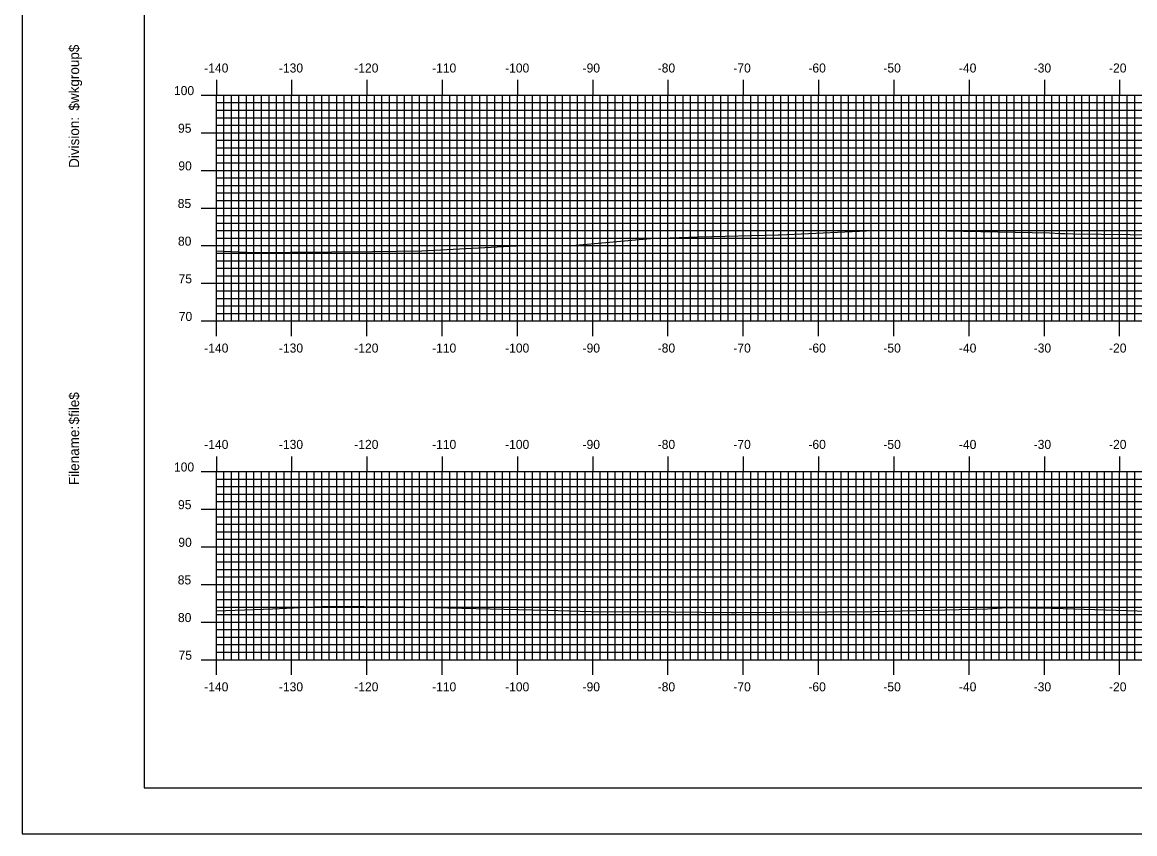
# Model space of a CAD drawing. Extents: x 856716 to 857060, y 364765 to 364985.
# Drawn here: x 856716.5 to 856864.3, y 364765.2 to 364873 of the extents above; entities that cross this region are included whole.
import ezdxf

# ---------------------------------------------------------------- set-up
doc = ezdxf.new("R2010")
doc.units = 0
for name, color, linetype in [('BORDER', 7, 'Continuous'), ('H_V ANNOTATION', 7, 'Continuous'), ('MAJOR', 7, 'Continuous'), ('MINOR', 7, 'Continuous'), ('PLOT BOUNDARY', 7, 'Continuous'), ('S_Roadway_Centerline', 7, 'Continuous')]:
    doc.layers.add(name, color=color, linetype=linetype)

msp = doc.modelspace()

# ---------------------------------------------------------------- linework, layer by layer
at = {"layer": 'BORDER'}
msp.add_lwpolyline([(856732.68, 364771.3), (857052.68, 364771.3), (857052.68, 364981.3), (856732.68, 364981.3)], close=True, dxfattribs=at)
at = {"layer": 'MAJOR'}
for p, q in [((856742.28, 364865.31), (856742.28, 364863.3)), ((856752.28, 364865.31), (856752.28, 364863.3)), ((856762.28, 364865.31), (856762.28, 364863.3)), ((856772.28, 364865.31), (856772.28, 364863.3)), ((856782.28, 364865.31), (856782.28, 364863.3)), ((856792.28, 364865.31), (856792.28, 364863.3)), ((856802.28, 364865.31), (856802.28, 364863.3)), ((856812.28, 364865.31), (856812.28, 364863.3)), ((856822.28, 364865.31), (856822.28, 364863.3)), ((856832.28, 364865.31), (856832.28, 364863.3)), ((856842.28, 364865.31), (856842.28, 364863.3)), ((856852.28, 364865.31), (856852.28, 364863.3)), ((856862.28, 364865.31), (856862.28, 364863.3)), ((856740.28, 364863.3), (856742.28, 364863.3)), ((856742.28, 364863.3), (857022.28, 364863.3)), ((856742.28, 364833.3), (856742.28, 364863.3)), ((856742.28, 364833.3), (856742.28, 364863.3)), ((856742.28, 364863.3), (857022.28, 364863.3)), ((856752.28, 364833.3), (856752.28, 364863.3)), ((856762.28, 364833.3), (856762.28, 364863.3)), ((856772.28, 364833.3), (856772.28, 364863.3)), ((856782.28, 364833.3), (856782.28, 364863.3)), ((856792.28, 364833.3), (856792.28, 364863.3)), ((856802.28, 364833.3), (856802.28, 364863.3)), ((856812.28, 364833.3), (856812.28, 364863.3)), ((856822.28, 364833.3), (856822.28, 364863.3)), ((856832.28, 364833.3), (856832.28, 364863.3)), ((856842.28, 364833.3), (856842.28, 364863.3)), ((856852.28, 364833.3), (856852.28, 364863.3)), ((856862.28, 364833.3), (856862.28, 364863.3)), ((856740.28, 364858.3), (856742.28, 364858.3)), ((856742.28, 364858.3), (857022.28, 364858.3)), ((856740.28, 364853.3), (856742.28, 364853.3)), ((856742.28, 364853.3), (857022.28, 364853.3)), ((856740.28, 364848.3), (856742.28, 364848.3)), ((856742.28, 364848.3), (857022.28, 364848.3)), ((856740.28, 364843.3), (856742.28, 364843.3)), ((856742.28, 364843.3), (857022.28, 364843.3)), ((856740.28, 364838.3), (856742.28, 364838.3)), ((856742.28, 364838.3), (857022.28, 364838.3)), ((856740.28, 364833.3), (856742.28, 364833.3)), ((856742.28, 364833.3), (857022.28, 364833.3)), ((856742.28, 364833.3), (857022.28, 364833.3)), ((856742.28, 364831.3), (856742.28, 364833.3)), ((856752.28, 364831.3), (856752.28, 364833.3)), ((856762.28, 364831.3), (856762.28, 364833.3)), ((856772.28, 364831.3), (856772.28, 364833.3)), ((856782.28, 364831.3), (856782.28, 364833.3)), ((856792.28, 364831.3), (856792.28, 364833.3)), ((856802.28, 364831.3), (856802.28, 364833.3)), ((856812.28, 364831.3), (856812.28, 364833.3)), ((856822.28, 364831.3), (856822.28, 364833.3)), ((856832.28, 364831.3), (856832.28, 364833.3)), ((856842.28, 364831.3), (856842.28, 364833.3)), ((856852.28, 364831.3), (856852.28, 364833.3)), ((856862.28, 364831.3), (856862.28, 364833.3)), ((856742.28, 364815.31), (856742.28, 364813.3)), ((856752.28, 364815.31), (856752.28, 364813.3)), ((856762.28, 364815.31), (856762.28, 364813.3)), ((856772.28, 364815.31), (856772.28, 364813.3)), ((856782.28, 364815.31), (856782.28, 364813.3)), ((856792.28, 364815.31), (856792.28, 364813.3)), ((856802.28, 364815.31), (856802.28, 364813.3)), ((856812.28, 364815.31), (856812.28, 364813.3)), ((856822.28, 364815.31), (856822.28, 364813.3)), ((856832.28, 364815.31), (856832.28, 364813.3)), ((856842.28, 364815.31), (856842.28, 364813.3)), ((856852.28, 364815.31), (856852.28, 364813.3)), ((856862.28, 364815.31), (856862.28, 364813.3)), ((856740.28, 364813.3), (856742.28, 364813.3)), ((856742.28, 364813.3), (857022.28, 364813.3)), ((856742.28, 364788.3), (856742.28, 364813.3)), ((856742.28, 364788.3), (856742.28, 364813.3)), ((856742.28, 364813.3), (857022.28, 364813.3)), ((856752.28, 364788.3), (856752.28, 364813.3)), ((856762.28, 364788.3), (856762.28, 364813.3)), ((856772.28, 364788.3), (856772.28, 364813.3)), ((856782.28, 364788.3), (856782.28, 364813.3)), ((856792.28, 364788.3), (856792.28, 364813.3)), ((856802.28, 364788.3), (856802.28, 364813.3)), ((856812.28, 364788.3), (856812.28, 364813.3)), ((856822.28, 364788.3), (856822.28, 364813.3)), ((856832.28, 364788.3), (856832.28, 364813.3)), ((856842.28, 364788.3), (856842.28, 364813.3)), ((856852.28, 364788.3), (856852.28, 364813.3)), ((856862.28, 364788.3), (856862.28, 364813.3)), ((856740.28, 364808.3), (856742.28, 364808.3)), ((856742.28, 364808.3), (857022.28, 364808.3)), ((856740.28, 364803.3), (856742.28, 364803.3)), ((856742.28, 364803.3), (857022.28, 364803.3)), ((856740.28, 364798.3), (856742.28, 364798.3)), ((856742.28, 364798.3), (857022.28, 364798.3)), ((856740.28, 364793.3), (856742.28, 364793.3)), ((856742.28, 364793.3), (857022.28, 364793.3)), ((856740.28, 364788.3), (856742.28, 364788.3)), ((856742.28, 364788.3), (857022.28, 364788.3)), ((856742.28, 364788.3), (857022.28, 364788.3)), ((856742.28, 364786.3), (856742.28, 364788.3)), ((856752.28, 364786.3), (856752.28, 364788.3)), ((856762.28, 364786.3), (856762.28, 364788.3)), ((856772.28, 364786.3), (856772.28, 364788.3)), ((856782.28, 364786.3), (856782.28, 364788.3)), ((856792.28, 364786.3), (856792.28, 364788.3)), ((856802.28, 364786.3), (856802.28, 364788.3)), ((856812.28, 364786.3), (856812.28, 364788.3)), ((856822.28, 364786.3), (856822.28, 364788.3)), ((856832.28, 364786.3), (856832.28, 364788.3)), ((856842.28, 364786.3), (856842.28, 364788.3)), ((856852.28, 364786.3), (856852.28, 364788.3)), ((856862.28, 364786.3), (856862.28, 364788.3))]:
    msp.add_line(p, q, dxfattribs=at)
at = {"layer": 'MINOR'}
for p, q in [((856743.28, 364833.3), (856743.28, 364863.3)), ((856744.28, 364833.3), (856744.28, 364863.3)), ((856745.28, 364833.3), (856745.28, 364863.3)), ((856746.28, 364833.3), (856746.28, 364863.3)), ((856747.28, 364833.3), (856747.28, 364863.3)), ((856748.28, 364833.3), (856748.28, 364863.3)), ((856749.28, 364833.3), (856749.28, 364863.3)), ((856750.28, 364833.3), (856750.28, 364863.3)), ((856751.28, 364833.3), (856751.28, 364863.3)), ((856753.28, 364833.3), (856753.28, 364863.3)), ((856754.28, 364833.3), (856754.28, 364863.3)), ((856755.28, 364833.3), (856755.28, 364863.3)), ((856756.28, 364833.3), (856756.28, 364863.3)), ((856757.28, 364833.3), (856757.28, 364863.3)), ((856758.28, 364833.3), (856758.28, 364863.3)), ((856759.28, 364833.3), (856759.28, 364863.3)), ((856760.28, 364833.3), (856760.28, 364863.3)), ((856761.28, 364833.3), (856761.28, 364863.3)), ((856763.28, 364833.3), (856763.28, 364863.3)), ((856764.28, 364833.3), (856764.28, 364863.3)), ((856765.28, 364833.3), (856765.28, 364863.3)), ((856766.28, 364833.3), (856766.28, 364863.3)), ((856767.28, 364833.3), (856767.28, 364863.3)), ((856768.28, 364833.3), (856768.28, 364863.3)), ((856769.28, 364833.3), (856769.28, 364863.3)), ((856770.28, 364833.3), (856770.28, 364863.3)), ((856771.28, 364833.3), (856771.28, 364863.3)), ((856773.28, 364833.3), (856773.28, 364863.3)), ((856774.28, 364833.3), (856774.28, 364863.3)), ((856775.28, 364833.3), (856775.28, 364863.3)), ((856776.28, 364833.3), (856776.28, 364863.3)), ((856777.28, 364833.3), (856777.28, 364863.3)), ((856778.28, 364833.3), (856778.28, 364863.3)), ((856779.28, 364833.3), (856779.28, 364863.3)), ((856780.28, 364833.3), (856780.28, 364863.3)), ((856781.28, 364833.3), (856781.28, 364863.3)), ((856783.28, 364833.3), (856783.28, 364863.3)), ((856784.28, 364833.3), (856784.28, 364863.3)), ((856785.28, 364833.3), (856785.28, 364863.3)), ((856786.28, 364833.3), (856786.28, 364863.3)), ((856787.28, 364833.3), (856787.28, 364863.3)), ((856788.28, 364833.3), (856788.28, 364863.3)), ((856789.28, 364833.3), (856789.28, 364863.3)), ((856790.28, 364833.3), (856790.28, 364863.3)), ((856791.28, 364833.3), (856791.28, 364863.3)), ((856793.28, 364833.3), (856793.28, 364863.3)), ((856794.28, 364833.3), (856794.28, 364863.3)), ((856795.28, 364833.3), (856795.28, 364863.3)), ((856796.28, 364833.3), (856796.28, 364863.3)), ((856797.28, 364833.3), (856797.28, 364863.3)), ((856798.28, 364833.3), (856798.28, 364863.3)), ((856799.28, 364833.3), (856799.28, 364863.3)), ((856800.28, 364833.3), (856800.28, 364863.3)), ((856801.28, 364833.3), (856801.28, 364863.3)), ((856803.28, 364833.3), (856803.28, 364863.3)), ((856804.28, 364833.3), (856804.28, 364863.3)), ((856805.28, 364833.3), (856805.28, 364863.3)), ((856806.28, 364833.3), (856806.28, 364863.3)), ((856807.28, 364833.3), (856807.28, 364863.3)), ((856808.28, 364833.3), (856808.28, 364863.3)), ((856809.28, 364833.3), (856809.28, 364863.3)), ((856810.28, 364833.3), (856810.28, 364863.3)), ((856811.28, 364833.3), (856811.28, 364863.3)), ((856813.28, 364833.3), (856813.28, 364863.3)), ((856814.28, 364833.3), (856814.28, 364863.3)), ((856815.28, 364833.3), (856815.28, 364863.3)), ((856816.28, 364833.3), (856816.28, 364863.3)), ((856817.28, 364833.3), (856817.28, 364863.3)), ((856818.28, 364833.3), (856818.28, 364863.3)), ((856819.28, 364833.3), (856819.28, 364863.3)), ((856820.28, 364833.3), (856820.28, 364863.3)), ((856821.28, 364833.3), (856821.28, 364863.3)), ((856823.28, 364833.3), (856823.28, 364863.3)), ((856824.28, 364833.3), (856824.28, 364863.3)), ((856825.28, 364833.3), (856825.28, 364863.3)), ((856826.28, 364833.3), (856826.28, 364863.3)), ((856827.28, 364833.3), (856827.28, 364863.3)), ((856828.28, 364833.3), (856828.28, 364863.3)), ((856829.28, 364833.3), (856829.28, 364863.3)), ((856830.28, 364833.3), (856830.28, 364863.3)), ((856831.28, 364833.3), (856831.28, 364863.3)), ((856833.28, 364833.3), (856833.28, 364863.3)), ((856834.28, 364833.3), (856834.28, 364863.3)), ((856835.28, 364833.3), (856835.28, 364863.3)), ((856836.28, 364833.3), (856836.28, 364863.3)), ((856837.28, 364833.3), (856837.28, 364863.3)), ((856838.28, 364833.3), (856838.28, 364863.3)), ((856839.28, 364833.3), (856839.28, 364863.3)), ((856840.28, 364833.3), (856840.28, 364863.3)), ((856841.28, 364833.3), (856841.28, 364863.3)), ((856843.28, 364833.3), (856843.28, 364863.3)), ((856844.28, 364833.3), (856844.28, 364863.3)), ((856845.28, 364833.3), (856845.28, 364863.3)), ((856846.28, 364833.3), (856846.28, 364863.3)), ((856847.28, 364833.3), (856847.28, 364863.3)), ((856848.28, 364833.3), (856848.28, 364863.3)), ((856849.28, 364833.3), (856849.28, 364863.3)), ((856850.28, 364833.3), (856850.28, 364863.3)), ((856851.28, 364833.3), (856851.28, 364863.3)), ((856853.28, 364833.3), (856853.28, 364863.3)), ((856854.28, 364833.3), (856854.28, 364863.3)), ((856855.28, 364833.3), (856855.28, 364863.3)), ((856856.28, 364833.3), (856856.28, 364863.3)), ((856857.28, 364833.3), (856857.28, 364863.3)), ((856858.28, 364833.3), (856858.28, 364863.3)), ((856859.28, 364833.3), (856859.28, 364863.3)), ((856860.28, 364833.3), (856860.28, 364863.3)), ((856861.28, 364833.3), (856861.28, 364863.3)), ((856863.28, 364833.3), (856863.28, 364863.3)), ((856864.28, 364833.3), (856864.28, 364863.3)), ((856742.28, 364862.3), (857022.28, 364862.3)), ((856742.28, 364862.3), (856744.29, 364862.3)), ((856742.28, 364861.3), (857022.28, 364861.3)), ((856742.28, 364861.3), (856744.29, 364861.3)), ((856742.28, 364860.3), (857022.28, 364860.3)), ((856742.28, 364860.3), (856744.29, 364860.3)), ((856742.28, 364859.3), (857022.28, 364859.3)), ((856742.28, 364859.3), (856744.29, 364859.3)), ((856742.28, 364857.3), (857022.28, 364857.3)), ((856742.28, 364857.3), (856744.29, 364857.3)), ((856742.28, 364856.3), (857022.28, 364856.3)), ((856742.28, 364856.3), (856744.29, 364856.3)), ((856742.28, 364855.3), (857022.28, 364855.3)), ((856742.28, 364855.3), (856744.29, 364855.3)), ((856742.28, 364854.3), (857022.28, 364854.3)), ((856742.28, 364854.3), (856744.29, 364854.3)), ((856742.28, 364852.3), (857022.28, 364852.3)), ((856742.28, 364852.3), (856744.29, 364852.3)), ((856742.28, 364851.3), (857022.28, 364851.3)), ((856742.28, 364851.3), (856744.29, 364851.3)), ((856742.28, 364850.3), (857022.28, 364850.3)), ((856742.28, 364850.3), (856744.29, 364850.3)), ((856742.28, 364849.3), (857022.28, 364849.3)), ((856742.28, 364849.3), (856744.29, 364849.3)), ((856742.28, 364847.3), (857022.28, 364847.3)), ((856742.28, 364847.3), (856744.29, 364847.3)), ((856742.28, 364846.3), (857022.28, 364846.3)), ((856742.28, 364846.3), (856744.29, 364846.3)), ((856742.28, 364845.3), (857022.28, 364845.3)), ((856742.28, 364845.3), (856744.29, 364845.3)), ((856742.28, 364844.3), (857022.28, 364844.3)), ((856742.28, 364844.3), (856744.29, 364844.3)), ((856742.28, 364842.3), (857022.28, 364842.3)), ((856742.28, 364842.3), (856744.29, 364842.3)), ((856742.28, 364841.3), (857022.28, 364841.3)), ((856742.28, 364841.3), (856744.29, 364841.3)), ((856742.28, 364840.3), (857022.28, 364840.3)), ((856742.28, 364840.3), (856744.29, 364840.3)), ((856742.28, 364839.3), (857022.28, 364839.3)), ((856742.28, 364839.3), (856744.29, 364839.3)), ((856742.28, 364837.3), (857022.28, 364837.3)), ((856742.28, 364837.3), (856744.29, 364837.3)), ((856742.28, 364836.3), (857022.28, 364836.3)), ((856742.28, 364836.3), (856744.29, 364836.3)), ((856742.28, 364835.3), (857022.28, 364835.3)), ((856742.28, 364835.3), (856744.29, 364835.3)), ((856742.28, 364834.3), (857022.28, 364834.3)), ((856742.28, 364834.3), (856744.29, 364834.3)), ((856743.28, 364788.3), (856743.28, 364813.3)), ((856744.28, 364788.3), (856744.28, 364813.3)), ((856745.28, 364788.3), (856745.28, 364813.3)), ((856746.28, 364788.3), (856746.28, 364813.3)), ((856747.28, 364788.3), (856747.28, 364813.3)), ((856748.28, 364788.3), (856748.28, 364813.3)), ((856749.28, 364788.3), (856749.28, 364813.3)), ((856750.28, 364788.3), (856750.28, 364813.3)), ((856751.28, 364788.3), (856751.28, 364813.3)), ((856753.28, 364788.3), (856753.28, 364813.3)), ((856754.28, 364788.3), (856754.28, 364813.3)), ((856755.28, 364788.3), (856755.28, 364813.3)), ((856756.28, 364788.3), (856756.28, 364813.3)), ((856757.28, 364788.3), (856757.28, 364813.3)), ((856758.28, 364788.3), (856758.28, 364813.3)), ((856759.28, 364788.3), (856759.28, 364813.3)), ((856760.28, 364788.3), (856760.28, 364813.3)), ((856761.28, 364788.3), (856761.28, 364813.3)), ((856763.28, 364788.3), (856763.28, 364813.3)), ((856764.28, 364788.3), (856764.28, 364813.3)), ((856765.28, 364788.3), (856765.28, 364813.3)), ((856766.28, 364788.3), (856766.28, 364813.3)), ((856767.28, 364788.3), (856767.28, 364813.3)), ((856768.28, 364788.3), (856768.28, 364813.3)), ((856769.28, 364788.3), (856769.28, 364813.3)), ((856770.28, 364788.3), (856770.28, 364813.3)), ((856771.28, 364788.3), (856771.28, 364813.3)), ((856773.28, 364788.3), (856773.28, 364813.3)), ((856774.28, 364788.3), (856774.28, 364813.3)), ((856775.28, 364788.3), (856775.28, 364813.3)), ((856776.28, 364788.3), (856776.28, 364813.3)), ((856777.28, 364788.3), (856777.28, 364813.3)), ((856778.28, 364788.3), (856778.28, 364813.3)), ((856779.28, 364788.3), (856779.28, 364813.3)), ((856780.28, 364788.3), (856780.28, 364813.3)), ((856781.28, 364788.3), (856781.28, 364813.3)), ((856783.28, 364788.3), (856783.28, 364813.3)), ((856784.28, 364788.3), (856784.28, 364813.3)), ((856785.28, 364788.3), (856785.28, 364813.3)), ((856786.28, 364788.3), (856786.28, 364813.3)), ((856787.28, 364788.3), (856787.28, 364813.3)), ((856788.28, 364788.3), (856788.28, 364813.3)), ((856789.28, 364788.3), (856789.28, 364813.3)), ((856790.28, 364788.3), (856790.28, 364813.3)), ((856791.28, 364788.3), (856791.28, 364813.3)), ((856793.28, 364788.3), (856793.28, 364813.3)), ((856794.28, 364788.3), (856794.28, 364813.3)), ((856795.28, 364788.3), (856795.28, 364813.3)), ((856796.28, 364788.3), (856796.28, 364813.3)), ((856797.28, 364788.3), (856797.28, 364813.3)), ((856798.28, 364788.3), (856798.28, 364813.3)), ((856799.28, 364788.3), (856799.28, 364813.3)), ((856800.28, 364788.3), (856800.28, 364813.3)), ((856801.28, 364788.3), (856801.28, 364813.3)), ((856803.28, 364788.3), (856803.28, 364813.3)), ((856804.28, 364788.3), (856804.28, 364813.3)), ((856805.28, 364788.3), (856805.28, 364813.3)), ((856806.28, 364788.3), (856806.28, 364813.3)), ((856807.28, 364788.3), (856807.28, 364813.3)), ((856808.28, 364788.3), (856808.28, 364813.3)), ((856809.28, 364788.3), (856809.28, 364813.3)), ((856810.28, 364788.3), (856810.28, 364813.3)), ((856811.28, 364788.3), (856811.28, 364813.3)), ((856813.28, 364788.3), (856813.28, 364813.3)), ((856814.28, 364788.3), (856814.28, 364813.3)), ((856815.28, 364788.3), (856815.28, 364813.3)), ((856816.28, 364788.3), (856816.28, 364813.3)), ((856817.28, 364788.3), (856817.28, 364813.3)), ((856818.28, 364788.3), (856818.28, 364813.3)), ((856819.28, 364788.3), (856819.28, 364813.3)), ((856820.28, 364788.3), (856820.28, 364813.3)), ((856821.28, 364788.3), (856821.28, 364813.3)), ((856823.28, 364788.3), (856823.28, 364813.3)), ((856824.28, 364788.3), (856824.28, 364813.3)), ((856825.28, 364788.3), (856825.28, 364813.3)), ((856826.28, 364788.3), (856826.28, 364813.3)), ((856827.28, 364788.3), (856827.28, 364813.3)), ((856828.28, 364788.3), (856828.28, 364813.3)), ((856829.28, 364788.3), (856829.28, 364813.3)), ((856830.28, 364788.3), (856830.28, 364813.3)), ((856831.28, 364788.3), (856831.28, 364813.3)), ((856833.28, 364788.3), (856833.28, 364813.3)), ((856834.28, 364788.3), (856834.28, 364813.3)), ((856835.28, 364788.3), (856835.28, 364813.3)), ((856836.28, 364788.3), (856836.28, 364813.3)), ((856837.28, 364788.3), (856837.28, 364813.3)), ((856838.28, 364788.3), (856838.28, 364813.3)), ((856839.28, 364788.3), (856839.28, 364813.3)), ((856840.28, 364788.3), (856840.28, 364813.3)), ((856841.28, 364788.3), (856841.28, 364813.3)), ((856843.28, 364788.3), (856843.28, 364813.3)), ((856844.28, 364788.3), (856844.28, 364813.3)), ((856845.28, 364788.3), (856845.28, 364813.3)), ((856846.28, 364788.3), (856846.28, 364813.3)), ((856847.28, 364788.3), (856847.28, 364813.3)), ((856848.28, 364788.3), (856848.28, 364813.3)), ((856849.28, 364788.3), (856849.28, 364813.3)), ((856850.28, 364788.3), (856850.28, 364813.3)), ((856851.28, 364788.3), (856851.28, 364813.3)), ((856853.28, 364788.3), (856853.28, 364813.3)), ((856854.28, 364788.3), (856854.28, 364813.3)), ((856855.28, 364788.3), (856855.28, 364813.3)), ((856856.28, 364788.3), (856856.28, 364813.3)), ((856857.28, 364788.3), (856857.28, 364813.3)), ((856858.28, 364788.3), (856858.28, 364813.3)), ((856859.28, 364788.3), (856859.28, 364813.3)), ((856860.28, 364788.3), (856860.28, 364813.3)), ((856861.28, 364788.3), (856861.28, 364813.3)), ((856863.28, 364788.3), (856863.28, 364813.3)), ((856864.28, 364788.3), (856864.28, 364813.3)), ((856742.28, 364812.3), (857022.28, 364812.3)), ((856742.28, 364812.3), (856744.29, 364812.3)), ((856742.28, 364811.3), (857022.28, 364811.3)), ((856742.28, 364811.3), (856744.29, 364811.3)), ((856742.28, 364810.3), (857022.28, 364810.3)), ((856742.28, 364810.3), (856744.29, 364810.3)), ((856742.28, 364809.3), (857022.28, 364809.3)), ((856742.28, 364809.3), (856744.29, 364809.3)), ((856742.28, 364807.3), (857022.28, 364807.3)), ((856742.28, 364807.3), (856744.29, 364807.3)), ((856742.28, 364806.3), (857022.28, 364806.3)), ((856742.28, 364806.3), (856744.29, 364806.3)), ((856742.28, 364805.3), (857022.28, 364805.3)), ((856742.28, 364805.3), (856744.29, 364805.3)), ((856742.28, 364804.3), (857022.28, 364804.3)), ((856742.28, 364804.3), (856744.29, 364804.3)), ((856742.28, 364802.3), (857022.28, 364802.3)), ((856742.28, 364802.3), (856744.29, 364802.3)), ((856742.28, 364801.3), (857022.28, 364801.3)), ((856742.28, 364801.3), (856744.29, 364801.3)), ((856742.28, 364800.3), (857022.28, 364800.3)), ((856742.28, 364800.3), (856744.29, 364800.3)), ((856742.28, 364799.3), (857022.28, 364799.3)), ((856742.28, 364799.3), (856744.29, 364799.3)), ((856742.28, 364797.3), (857022.28, 364797.3)), ((856742.28, 364797.3), (856744.29, 364797.3)), ((856742.28, 364796.3), (857022.28, 364796.3)), ((856742.28, 364796.3), (856744.29, 364796.3)), ((856742.28, 364795.3), (857022.28, 364795.3)), ((856742.28, 364795.3), (856744.29, 364795.3)), ((856742.28, 364794.3), (857022.28, 364794.3)), ((856742.28, 364794.3), (856744.29, 364794.3)), ((856742.28, 364792.3), (857022.28, 364792.3)), ((856742.28, 364792.3), (856744.29, 364792.3)), ((856742.28, 364791.3), (857022.28, 364791.3)), ((856742.28, 364791.3), (856744.29, 364791.3)), ((856742.28, 364790.3), (857022.28, 364790.3)), ((856742.28, 364790.3), (856744.29, 364790.3)), ((856742.28, 364789.3), (857022.28, 364789.3)), ((856742.28, 364789.3), (856744.29, 364789.3))]:
    msp.add_line(p, q, dxfattribs=at)
at = {"layer": 'PLOT BOUNDARY'}
msp.add_lwpolyline([(856716.49, 364765.18), (857056.49, 364765.18), (857056.49, 364985.18), (856716.49, 364985.18)], close=True, dxfattribs=at)
at = {"layer": 'S_Roadway_Centerline'}
for points in [[(856742.28, 364842.63), (856746.13, 364842.43), (856746.38, 364842.42), (856746.62, 364842.4), (856763.01, 364842.52), (856769.57, 364842.63), (856782.11, 364843.26), (856790.02, 364843.37), (856799.95, 364844.23), (856806.34, 364844.46), (856816.92, 364844.74), (856817.11, 364844.75), (856830.59, 364845.34), (856836.97, 364845.33), (856852.96, 364844.99), (856854.42, 364844.92), (856855.01, 364844.93), (856856.1, 364844.88), (856867.46, 364844.74)], [(856742.28, 364794.78), (856749.73, 364795.08), (856756.2, 364795.36), (856761.94, 364795.36), (856767.36, 364795.33), (856786.19, 364794.88), (856793.53, 364794.64), (856798.72, 364794.69), (856810.67, 364794.59), (856811.1, 364794.59), (856829.61, 364794.71), (856844.73, 364795.07), (856847.33, 364795.24), (856853.38, 364795.15), (856867.43, 364794.72)]]:
    msp.add_lwpolyline(points, dxfattribs=at)

# ---------------------------------------------------------------- texts
at = {"layer": 'BORDER'}
for s, p in [('$wkgroup$', (856724.05, 364861.24)), ('Division:', (856724.05, 364853.63)), ('$file$', (856724.05, 364819.55)), ('Filename:', (856724.05, 364811.5))]:
    msp.add_text(s, height=1.339, rotation=90, dxfattribs=at).set_placement(p)
at = {"layer": 'H_V ANNOTATION'}
for s, p in [('-140', (856740.67, 364866.3)), ('-130', (856750.59, 364866.3)), ('-120', (856760.6, 364866.3)), ('-110', (856770.94, 364866.3)), ('-100', (856780.64, 364866.3)), ('-90', (856790.93, 364866.3)), ('-80', (856800.91, 364866.3)), ('-70', (856810.96, 364866.3)), ('-60', (856820.93, 364866.3)), ('-50', (856830.89, 364866.3)), ('-40', (856840.93, 364866.3)), ('-30', (856850.86, 364866.3)), ('-20', (856860.87, 364866.3)), ('100', (856736.65, 364863.3)), ('95', (856737.19, 364858.3)), ('90', (856737.23, 364853.3)), ('85', (856737.15, 364848.3)), ('80', (856737.18, 364843.3)), ('75', (856737.26, 364838.3)), ('70', (856737.29, 364833.3)), ('-140', (856740.67, 364829.1)), ('-130', (856750.59, 364829.1)), ('-120', (856760.6, 364829.1)), ('-110', (856770.94, 364829.1)), ('-100', (856780.64, 364829.1)), ('-90', (856790.93, 364829.1)), ('-80', (856800.91, 364829.1)), ('-70', (856810.96, 364829.1)), ('-60', (856820.93, 364829.1)), ('-50', (856830.89, 364829.1)), ('-40', (856840.93, 364829.1)), ('-30', (856850.86, 364829.1)), ('-20', (856860.87, 364829.1)), ('-140', (856740.67, 364816.3)), ('-130', (856750.59, 364816.3)), ('-120', (856760.6, 364816.3)), ('-110', (856770.94, 364816.3)), ('-100', (856780.64, 364816.3)), ('-90', (856790.93, 364816.3)), ('-80', (856800.91, 364816.3)), ('-70', (856810.96, 364816.3)), ('-60', (856820.93, 364816.3)), ('-50', (856830.89, 364816.3)), ('-40', (856840.93, 364816.3)), ('-30', (856850.86, 364816.3)), ('-20', (856860.87, 364816.3)), ('100', (856736.65, 364813.3)), ('95', (856737.19, 364808.3)), ('90', (856737.23, 364803.3)), ('85', (856737.15, 364798.3)), ('80', (856737.18, 364793.3)), ('75', (856737.26, 364788.3)), ('-140', (856740.67, 364784.1)), ('-130', (856750.59, 364784.1)), ('-120', (856760.6, 364784.1)), ('-110', (856770.94, 364784.1)), ('-100', (856780.64, 364784.1)), ('-90', (856790.93, 364784.1)), ('-80', (856800.91, 364784.1)), ('-70', (856810.96, 364784.1)), ('-60', (856820.93, 364784.1)), ('-50', (856830.89, 364784.1)), ('-40', (856840.93, 364784.1)), ('-30', (856850.86, 364784.1)), ('-20', (856860.87, 364784.1))]:
    msp.add_text(s, height=1.2, dxfattribs=at).set_placement(p)
at = {"layer": 'MAJOR'}
for p in [(856742.27, 364833.3), (856742.27, 364788.3)]:
    msp.add_text('-', height=0.012, dxfattribs=at).set_placement(p)

doc.saveas('drawing.dxf')
